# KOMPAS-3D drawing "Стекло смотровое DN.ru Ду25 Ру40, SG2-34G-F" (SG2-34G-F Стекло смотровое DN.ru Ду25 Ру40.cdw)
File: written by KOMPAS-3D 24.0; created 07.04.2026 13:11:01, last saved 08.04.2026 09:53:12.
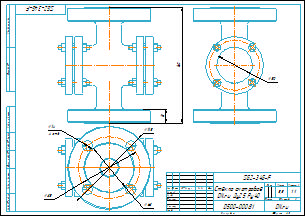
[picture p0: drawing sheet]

Document properties: Автор: Main; Форматы листов документа: A3; Полное имя файла: SG2-34G-F Стекло смотровое DN.ru Ду25 Ру40.m3d; Масса: 5.5; Наименование: Стекло смотровое DN.ru Ду25 Ру40; Количество листов документа: 1; Примечание: D500-00081

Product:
- Body: Тело 1  | qty 1
    Масса: 4.394636
- Part/product: Стекло смотровое DN.ru Ду25 Ру40  | designation SG2-34G-F
    Масса: 5.5
    Раздел спецификации: Прочие изделия
    Примечание: D500-00081

Views: Вид 1, Снизу, Проекционный вид 2
Referenced files in D:\DN.ru Аутсерс\Стекло смотровое DN.ru\Стекло смотровое DN.ru SG2-34G-F тип В ГОСТ 21836-2021 Ду100 Ру16, углеродистая сталь, фланцевое\: SG2-34G-F тип В Стекло смотровое DN.ru Ду100 Ру16.m3d, SG2-34G-F тип ВСтекло смотровое DN.ru Ду100 Ру16.cdw
Referenced files in D:\DN.ru Аутсерс\Стекло смотровое DN.ru\SG2-34G-F Стекло смотровое DN.ru Ду25 Ру40\: SG2-34G-F Стекло смотровое DN.ru Ду25 Ру40.m3d
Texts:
  SG2-34G-F
  Стекло смотровое
  DN.ru Ду25 Ру40
  Стекло смотровое DN.ru Ду25 Ру40
  SG2-34G-F Стекло смотровое DN.ru Ду25 Ру40
Dimensions and other numbers on the sheet: 0; 3; 2; 4; 160; 18; 14; 4 отв.; 85; 115; 68; 1:1; 1; 5,5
